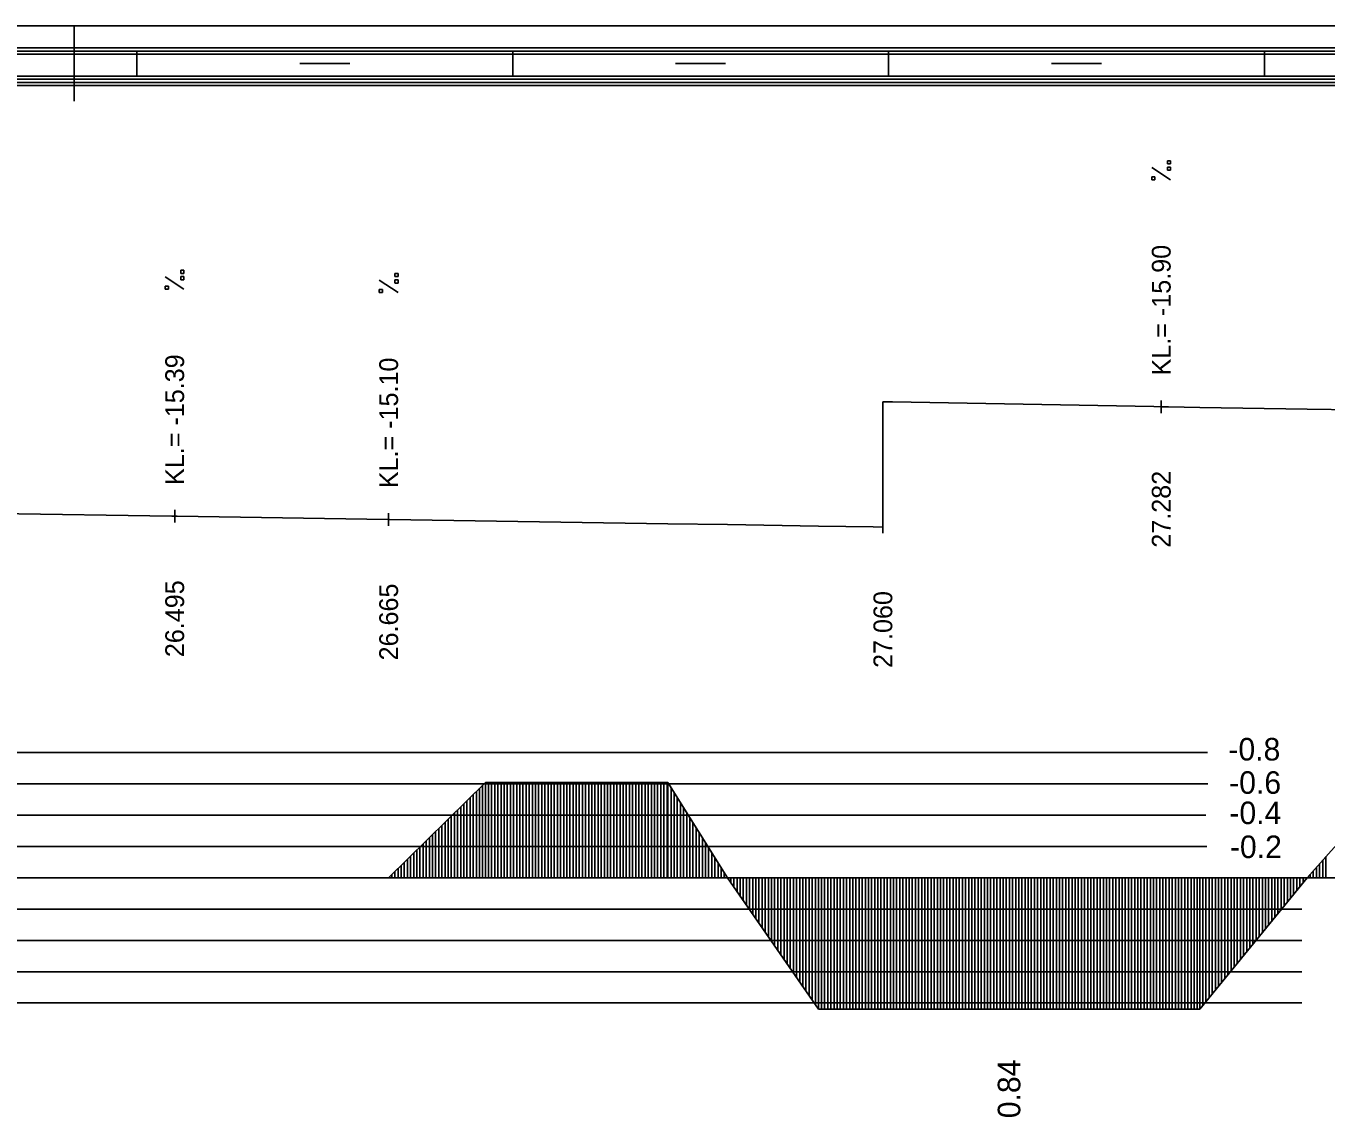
# Model space of a CAD drawing. Extents: x 2 to 10148, y 0 to 380.
# Drawn here: x 2936.2 to 3039.9, y 292.9 to 380 of the extents above; entities that cross this region are included whole.
import ezdxf

# ---------------------------------------------------------------- set-up
doc = ezdxf.new("R2010")
doc.units = 0
for name, color, linetype in [('NIVELETA_CARA', 7, 'Continuous'), ('NIVELETA_TEXT', 7, 'Continuous'), ('RAM', 7, 'Continuous'), ('ZRYCHL_CARA_C', 7, 'Continuous'), ('ZRYCHL_RASTR', 7, 'Continuous'), ('ZRYCHL_TEXT', 7, 'Continuous')]:
    doc.layers.add(name, color=color, linetype=linetype)

msp = doc.modelspace()

# ---------------------------------------------------------------- linework, layer by layer
at = {"layer": 'NIVELETA_CARA'}
for p, q in [((3004.55, 340), (3004.55, 350)), ((3004.55, 350), (3005.33, 349.99)), ((3005.33, 349.99), (3026.19, 349.61)), ((3026.77, 349.1), (3026.77, 350.1)), ((3026.19, 349.61), (3026.77, 349.6)), ((3026.77, 349.6), (3027.34, 349.59)), ((3027.34, 349.59), (3029.84, 349.55)), ((3029.84, 349.55), (3038.41, 349.41)), ((3038.41, 349.41), (3047.31, 349.27)), ((3004.55, 343.77), (3004.55, 346.25)), ((2918.57, 341.34), (2947.8, 340.86)), ((2947.8, 340.86), (2948.02, 340.86)), ((2948.02, 340.36), (2948.02, 341.36)), ((2948.02, 340.86), (2948.23, 340.86)), ((2948.23, 340.86), (2965.03, 340.6)), ((2965.03, 340.6), (2965.1, 340.6)), ((2965.1, 340.1), (2965.1, 341.1)), ((2965.1, 340.6), (2965.17, 340.59)), ((2965.17, 340.59), (2987.39, 340.26)), ((3004.55, 339.5), (3004.55, 340.5)), ((2987.39, 340.26), (2992.16, 340.19)), ((2992.16, 340.19), (2999.4, 340.08)), ((2999.4, 340.08), (3003.78, 340.01)), ((3003.78, 340.01), (3004.55, 340))]:
    msp.add_line(p, q, dxfattribs=at)
at = {"layer": 'NIVELETA_TEXT'}
for p, q in [((3027.51, 367.72), (3026.02, 368.71)), ((3027.52, 369.24), (3027.27, 369.24)), ((3027.27, 369.24), (3027.27, 369)), ((3027.27, 369), (3027.27, 368.99)), ((3027.27, 368.99), (3027.52, 368.99)), ((3027.52, 368.73), (3027.27, 368.73)), ((3027.27, 368.73), (3027.27, 368.48)), ((3027.27, 368.48), (3027.52, 368.48)), ((3027.27, 368.48), (3027.27, 368.48)), ((3027.52, 368.99), (3027.52, 369.24)), ((3027.52, 368.48), (3027.52, 368.73)), ((3026.27, 367.97), (3026.02, 367.97)), ((3026.02, 367.97), (3026.02, 367.73)), ((3026.02, 367.73), (3026.03, 367.72)), ((3026.02, 367.72), (3026.27, 367.72)), ((3026.27, 367.72), (3026.27, 367.97)), ((2948.76, 360.5), (2948.52, 360.5)), ((2948.52, 360.5), (2948.52, 360.26)), ((2948.52, 360.26), (2948.52, 360.25)), ((2948.52, 360.25), (2948.76, 360.25)), ((2948.76, 360.25), (2948.76, 360.5)), ((2965.85, 360.24), (2965.6, 360.24)), ((2965.6, 360.24), (2965.6, 360)), ((2965.85, 359.99), (2965.85, 360.24)), ((2948.76, 358.99), (2947.27, 359.98)), ((2947.52, 359.23), (2947.27, 359.23)), ((2947.27, 359.23), (2947.27, 358.99)), ((2947.52, 358.99), (2947.52, 359.23)), ((2948.76, 359.99), (2948.52, 359.99)), ((2948.52, 359.99), (2948.52, 359.75)), ((2948.52, 359.75), (2948.52, 359.74)), ((2948.52, 359.74), (2948.76, 359.74)), ((2948.76, 359.74), (2948.76, 359.99)), ((2965.85, 358.72), (2964.35, 359.71)), ((2965.6, 360), (2965.61, 359.99)), ((2965.6, 359.99), (2965.85, 359.99)), ((2965.85, 359.73), (2965.6, 359.73)), ((2965.6, 359.73), (2965.6, 359.49)), ((2965.6, 359.49), (2965.61, 359.48)), ((2965.6, 359.48), (2965.85, 359.48)), ((2965.85, 359.48), (2965.85, 359.73)), ((2947.27, 358.99), (2947.52, 358.99)), ((2947.27, 358.99), (2947.27, 358.99)), ((2964.6, 358.97), (2964.35, 358.97)), ((2964.35, 358.97), (2964.35, 358.73)), ((2964.35, 358.73), (2964.36, 358.72)), ((2964.35, 358.72), (2964.6, 358.72)), ((2964.6, 358.72), (2964.6, 358.97))]:
    msp.add_line(p, q, dxfattribs=at)
at = {"layer": 'RAM'}
for p, q in [((3155.54, 380), (2328.7, 380)), ((2940, 374), (2940, 380)), ((3155.54, 378.25), (2328.7, 378.25)), ((3155.54, 378), (2328.7, 378)), ((3155.54, 377.75), (2328.7, 377.75)), ((2945, 376), (2945, 378)), ((2975, 376), (2975, 378)), ((3005, 376), (3005, 378)), ((3035, 376), (3035, 378)), ((2958, 377), (2962, 377)), ((2988, 377), (2992, 377)), ((3018, 377), (3022, 377)), ((3155.54, 376), (2328.7, 376)), ((3155.54, 375.75), (2328.7, 375.75)), ((3155.54, 375.5), (2328.7, 375.5)), ((3155.54, 375.25), (2328.7, 375.25))]:
    msp.add_line(p, q, dxfattribs=at)
at = {"layer": 'ZRYCHL_CARA_C'}
for p, q in [((3038.41, 312), (3047.31, 322.02)), ((2965.1, 312), (2972.82, 319.6)), ((2971.85, 312), (2971.85, 318.64)), ((2972.1, 312), (2972.1, 318.89)), ((2972.35, 312), (2972.35, 319.14)), ((2972.6, 312), (2972.6, 319.38)), ((2972.82, 312), (2972.82, 319.6)), ((2972.82, 319.6), (2987.39, 319.6)), ((2973.07, 312), (2973.07, 319.6)), ((2973.32, 312), (2973.32, 319.6)), ((2973.57, 312), (2973.57, 319.6)), ((2973.82, 312), (2973.82, 319.6)), ((2974.07, 312), (2974.07, 319.6)), ((2974.32, 312), (2974.32, 319.6)), ((2974.57, 312), (2974.57, 319.6)), ((2974.82, 312), (2974.82, 319.6)), ((2975.07, 312), (2975.07, 319.6)), ((2975.32, 312), (2975.32, 319.6)), ((2975.57, 312), (2975.57, 319.6)), ((2975.82, 312), (2975.82, 319.6)), ((2976.07, 312), (2976.07, 319.6)), ((2976.32, 312), (2976.32, 319.6)), ((2976.57, 312), (2976.57, 319.6)), ((2976.82, 312), (2976.82, 319.6)), ((2977.07, 312), (2977.07, 319.6)), ((2977.32, 312), (2977.32, 319.6)), ((2977.57, 312), (2977.57, 319.6)), ((2977.82, 312), (2977.82, 319.6)), ((2978.07, 312), (2978.07, 319.6)), ((2978.32, 312), (2978.32, 319.6)), ((2978.57, 312), (2978.57, 319.6)), ((2978.82, 312), (2978.82, 319.6)), ((2979.07, 312), (2979.07, 319.6)), ((2979.32, 312), (2979.32, 319.6)), ((2979.57, 312), (2979.57, 319.6)), ((2979.82, 312), (2979.82, 319.6)), ((2980.07, 312), (2980.07, 319.6)), ((2980.32, 312), (2980.32, 319.6)), ((2980.57, 312), (2980.57, 319.6)), ((2980.82, 312), (2980.82, 319.6)), ((2981.07, 312), (2981.07, 319.6)), ((2981.32, 312), (2981.32, 319.6)), ((2981.57, 312), (2981.57, 319.6)), ((2981.82, 312), (2981.82, 319.6)), ((2982.07, 312), (2982.07, 319.6)), ((2982.32, 312), (2982.32, 319.6)), ((2982.57, 312), (2982.57, 319.6)), ((2982.82, 312), (2982.82, 319.6)), ((2983.07, 312), (2983.07, 319.6)), ((2983.32, 312), (2983.32, 319.6)), ((2983.57, 312), (2983.57, 319.6)), ((2983.82, 312), (2983.82, 319.6)), ((2984.07, 312), (2984.07, 319.6)), ((2984.32, 312), (2984.32, 319.6)), ((2984.57, 312), (2984.57, 319.6)), ((2984.82, 312), (2984.82, 319.6)), ((2985.07, 312), (2985.07, 319.6)), ((2985.32, 312), (2985.32, 319.6)), ((2985.57, 312), (2985.57, 319.6)), ((2985.82, 312), (2985.82, 319.6)), ((2986.07, 312), (2986.07, 319.6)), ((2986.32, 312), (2986.32, 319.6)), ((2986.57, 312), (2986.57, 319.6)), ((2986.82, 312), (2986.82, 319.6)), ((2987.07, 312), (2987.07, 319.6)), ((2987.32, 312), (2987.32, 319.6)), ((2987.39, 312), (2987.39, 319.6)), ((2987.39, 319.6), (2992.16, 312)), ((2987.64, 312), (2987.64, 319.2)), ((2987.89, 312), (2987.89, 318.8)), ((2970.85, 312), (2970.85, 317.66)), ((2971.1, 312), (2971.1, 317.91)), ((2971.35, 312), (2971.35, 318.15)), ((2971.6, 312), (2971.6, 318.4)), ((2988.14, 312), (2988.14, 318.4)), ((2988.39, 312), (2988.39, 318)), ((2988.64, 312), (2988.64, 317.61)), ((2969.85, 312), (2969.85, 316.68)), ((2970.1, 312), (2970.1, 316.92)), ((2970.35, 312), (2970.35, 317.17)), ((2970.6, 312), (2970.6, 317.41)), ((2988.89, 312), (2988.89, 317.21)), ((2989.14, 312), (2989.14, 316.81)), ((2968.85, 312), (2968.85, 315.69)), ((2969.1, 312), (2969.1, 315.94)), ((2969.35, 312), (2969.35, 316.18)), ((2969.6, 312), (2969.6, 316.43)), ((2989.39, 312), (2989.39, 316.41)), ((2989.64, 312), (2989.64, 316.01)), ((2989.89, 312), (2989.89, 315.61)), ((2967.6, 312), (2967.6, 314.46)), ((2967.85, 312), (2967.85, 314.71)), ((2968.1, 312), (2968.1, 314.95)), ((2968.35, 312), (2968.35, 315.2)), ((2968.6, 312), (2968.6, 315.45)), ((2990.14, 312), (2990.14, 315.22)), ((2990.39, 312), (2990.39, 314.82)), ((2966.6, 312), (2966.6, 313.48)), ((2966.85, 312), (2966.85, 313.72)), ((2967.1, 312), (2967.1, 313.97)), ((2967.35, 312), (2967.35, 314.21)), ((2990.64, 312), (2990.64, 314.42)), ((2990.89, 312), (2990.89, 314.02)), ((2991.14, 312), (2991.14, 313.62)), ((3039.66, 312), (3039.66, 313.41)), ((3039.91, 312), (3039.91, 313.69)), ((2965.6, 312), (2965.6, 312.49)), ((2965.85, 312), (2965.85, 312.74)), ((2966.1, 312), (2966.1, 312.98)), ((2966.35, 312), (2966.35, 313.23)), ((2991.39, 312), (2991.39, 313.23)), ((2991.64, 312), (2991.64, 312.83)), ((2991.89, 312), (2991.89, 312.43)), ((3038.91, 312), (3038.91, 312.56)), ((3039.16, 312), (3039.16, 312.84)), ((3039.41, 312), (3039.41, 313.12)), ((2328.7, 312), (3155.54, 312)), ((2965.35, 312), (2965.35, 312.25)), ((2992.14, 312), (2992.14, 312.03)), ((2992.16, 312), (2999.4, 301.5)), ((2992.41, 312), (2992.41, 311.64)), ((2992.66, 312), (2992.66, 311.28)), ((2992.91, 312), (2992.91, 310.91)), ((2993.16, 312), (2993.16, 310.55)), ((2993.41, 312), (2993.41, 310.19)), ((2993.66, 312), (2993.66, 309.83)), ((2993.91, 312), (2993.91, 309.46)), ((2994.16, 312), (2994.16, 309.1)), ((2994.41, 312), (2994.41, 308.74)), ((2994.66, 312), (2994.66, 308.38)), ((2994.91, 312), (2994.91, 308.01)), ((2995.16, 312), (2995.16, 307.65)), ((2995.41, 312), (2995.41, 307.29)), ((2995.66, 312), (2995.66, 306.93)), ((2995.91, 312), (2995.91, 306.56)), ((2996.16, 312), (2996.16, 306.2)), ((2996.41, 312), (2996.41, 305.84)), ((2996.66, 312), (2996.66, 305.48)), ((2996.91, 312), (2996.91, 305.11)), ((2997.16, 312), (2997.16, 304.75)), ((2997.41, 312), (2997.41, 304.39)), ((2997.66, 312), (2997.66, 304.03)), ((2997.91, 312), (2997.91, 303.66)), ((2998.16, 312), (2998.16, 303.3)), ((2998.41, 312), (2998.41, 302.94)), ((2998.66, 312), (2998.66, 302.58)), ((2998.91, 312), (2998.91, 302.21)), ((2999.16, 312), (2999.16, 301.85)), ((2999.4, 312), (2999.4, 301.5)), ((2999.65, 312), (2999.65, 301.5)), ((2999.9, 312), (2999.9, 301.5)), ((3000.15, 312), (3000.15, 301.5)), ((3000.4, 312), (3000.4, 301.5)), ((3000.65, 312), (3000.65, 301.5)), ((3000.9, 312), (3000.9, 301.5)), ((3001.15, 312), (3001.15, 301.5)), ((3001.4, 312), (3001.4, 301.5)), ((3001.65, 312), (3001.65, 301.5)), ((3001.9, 312), (3001.9, 301.5)), ((3002.15, 312), (3002.15, 301.5)), ((3002.4, 312), (3002.4, 301.5)), ((3002.65, 312), (3002.65, 301.5)), ((3002.9, 312), (3002.9, 301.5)), ((3003.15, 312), (3003.15, 301.5)), ((3003.4, 312), (3003.4, 301.5)), ((3003.65, 312), (3003.65, 301.5)), ((3003.9, 312), (3003.9, 301.5)), ((3004.15, 312), (3004.15, 301.5)), ((3004.4, 312), (3004.4, 301.5)), ((3004.65, 312), (3004.65, 301.5)), ((3004.9, 312), (3004.9, 301.5)), ((3005.15, 312), (3005.15, 301.5)), ((3005.4, 312), (3005.4, 301.5)), ((3005.65, 312), (3005.65, 301.5)), ((3005.9, 312), (3005.9, 301.5)), ((3006.15, 312), (3006.15, 301.5)), ((3006.4, 312), (3006.4, 301.5)), ((3006.65, 312), (3006.65, 301.5)), ((3006.9, 312), (3006.9, 301.5)), ((3007.15, 312), (3007.15, 301.5)), ((3007.4, 312), (3007.4, 301.5)), ((3007.65, 312), (3007.65, 301.5)), ((3007.9, 312), (3007.9, 301.5)), ((3008.15, 312), (3008.15, 301.5)), ((3008.4, 312), (3008.4, 301.5)), ((3008.65, 312), (3008.65, 301.5)), ((3008.9, 312), (3008.9, 301.5)), ((3009.15, 312), (3009.15, 301.5)), ((3009.4, 312), (3009.4, 301.5)), ((3009.65, 312), (3009.65, 301.5)), ((3009.9, 312), (3009.9, 301.5)), ((3010.15, 312), (3010.15, 301.5)), ((3010.4, 312), (3010.4, 301.5)), ((3010.65, 312), (3010.65, 301.5)), ((3010.9, 312), (3010.9, 301.5)), ((3011.15, 312), (3011.15, 301.5)), ((3011.4, 312), (3011.4, 301.5)), ((3011.65, 312), (3011.65, 301.5)), ((3011.9, 312), (3011.9, 301.5)), ((3012.15, 312), (3012.15, 301.5)), ((3012.4, 312), (3012.4, 301.5)), ((3012.65, 312), (3012.65, 301.5)), ((3012.9, 312), (3012.9, 301.5)), ((3013.15, 312), (3013.15, 301.5)), ((3013.4, 312), (3013.4, 301.5)), ((3013.65, 312), (3013.65, 301.5)), ((3013.9, 312), (3013.9, 301.5)), ((3014.15, 312), (3014.15, 301.5)), ((3014.4, 312), (3014.4, 301.5)), ((3014.65, 312), (3014.65, 301.5)), ((3014.9, 312), (3014.9, 301.5)), ((3015.15, 312), (3015.15, 301.5)), ((3015.4, 312), (3015.4, 301.5)), ((3015.65, 312), (3015.65, 301.5)), ((3015.9, 312), (3015.9, 301.5)), ((3016.15, 312), (3016.15, 301.5)), ((3016.4, 312), (3016.4, 301.5)), ((3016.65, 312), (3016.65, 301.5)), ((3016.9, 312), (3016.9, 301.5)), ((3017.15, 312), (3017.15, 301.5)), ((3017.4, 312), (3017.4, 301.5)), ((3017.65, 312), (3017.65, 301.5)), ((3017.9, 312), (3017.9, 301.5)), ((3018.15, 312), (3018.15, 301.5)), ((3018.4, 312), (3018.4, 301.5)), ((3018.65, 312), (3018.65, 301.5)), ((3018.9, 312), (3018.9, 301.5)), ((3019.15, 312), (3019.15, 301.5)), ((3019.4, 312), (3019.4, 301.5)), ((3019.65, 312), (3019.65, 301.5)), ((3019.9, 312), (3019.9, 301.5)), ((3020.15, 312), (3020.15, 301.5)), ((3020.4, 312), (3020.4, 301.5)), ((3020.65, 312), (3020.65, 301.5)), ((3020.9, 312), (3020.9, 301.5)), ((3021.15, 312), (3021.15, 301.5)), ((3021.4, 312), (3021.4, 301.5)), ((3021.65, 312), (3021.65, 301.5)), ((3021.9, 312), (3021.9, 301.5)), ((3022.15, 312), (3022.15, 301.5)), ((3022.4, 312), (3022.4, 301.5)), ((3022.65, 312), (3022.65, 301.5)), ((3022.9, 312), (3022.9, 301.5)), ((3023.15, 312), (3023.15, 301.5)), ((3023.4, 312), (3023.4, 301.5)), ((3023.65, 312), (3023.65, 301.5)), ((3023.9, 312), (3023.9, 301.5)), ((3024.15, 312), (3024.15, 301.5)), ((3024.4, 312), (3024.4, 301.5)), ((3024.65, 312), (3024.65, 301.5)), ((3024.9, 312), (3024.9, 301.5)), ((3025.15, 312), (3025.15, 301.5)), ((3025.4, 312), (3025.4, 301.5)), ((3025.65, 312), (3025.65, 301.5)), ((3025.9, 312), (3025.9, 301.5)), ((3026.15, 312), (3026.15, 301.5)), ((3026.4, 312), (3026.4, 301.5)), ((3026.65, 312), (3026.65, 301.5)), ((3026.9, 312), (3026.9, 301.5)), ((3027.15, 312), (3027.15, 301.5)), ((3027.4, 312), (3027.4, 301.5)), ((3027.65, 312), (3027.65, 301.5)), ((3027.9, 312), (3027.9, 301.5)), ((3028.15, 312), (3028.15, 301.5)), ((3028.4, 312), (3028.4, 301.5)), ((3028.65, 312), (3028.65, 301.5)), ((3028.9, 312), (3028.9, 301.5)), ((3029.15, 312), (3029.15, 301.5)), ((3029.4, 312), (3029.4, 301.5)), ((3029.65, 312), (3029.65, 301.5)), ((3029.84, 312), (3029.84, 301.5)), ((3029.84, 301.5), (3038.41, 312)), ((3030.09, 312), (3030.09, 301.81)), ((3030.34, 312), (3030.34, 302.12)), ((3030.59, 312), (3030.59, 302.42)), ((3030.84, 312), (3030.84, 302.73)), ((3031.09, 312), (3031.09, 303.04)), ((3031.34, 312), (3031.34, 303.34)), ((3031.59, 312), (3031.59, 303.65)), ((3031.84, 312), (3031.84, 303.95)), ((3032.09, 312), (3032.09, 304.26)), ((3032.34, 312), (3032.34, 304.57)), ((3032.59, 312), (3032.59, 304.87)), ((3032.84, 312), (3032.84, 305.18)), ((3033.09, 312), (3033.09, 305.48)), ((3033.34, 312), (3033.34, 305.79)), ((3033.59, 312), (3033.59, 306.1)), ((3033.84, 312), (3033.84, 306.4)), ((3034.09, 312), (3034.09, 306.71)), ((3034.34, 312), (3034.34, 307.02)), ((3034.59, 312), (3034.59, 307.32)), ((3034.84, 312), (3034.84, 307.63)), ((3035.09, 312), (3035.09, 307.93)), ((3035.34, 312), (3035.34, 308.24)), ((3035.59, 312), (3035.59, 308.55)), ((3035.84, 312), (3035.84, 308.85)), ((3036.09, 312), (3036.09, 309.16)), ((3036.34, 312), (3036.34, 309.47)), ((3036.59, 312), (3036.59, 309.77)), ((3036.84, 312), (3036.84, 310.08)), ((3037.09, 312), (3037.09, 310.38)), ((3037.34, 312), (3037.34, 310.69)), ((3037.59, 312), (3037.59, 311)), ((3037.84, 312), (3037.84, 311.3)), ((3038.09, 312), (3038.09, 311.61)), ((3038.34, 312), (3038.34, 311.92)), ((3038.66, 312), (3038.66, 312.28)), ((2999.4, 301.5), (3029.84, 301.5))]:
    msp.add_line(p, q, dxfattribs=at)
at = {"layer": 'ZRYCHL_RASTR'}
for p, q in [((2632, 322), (3030.47, 322)), ((2632, 319.5), (3030.48, 319.5)), ((2632, 317), (3030.32, 317)), ((2632, 314.5), (3030.4, 314.5)), ((2842, 309.5), (3038, 309.5)), ((2842, 307), (3038, 307)), ((2842, 304.5), (3038, 304.5)), ((2842, 302), (3038, 302))]:
    msp.add_line(p, q, dxfattribs=at)

# ---------------------------------------------------------------- texts
at = {"layer": 'NIVELETA_TEXT'}
for s, p in [('KL.= -15.90', (3027.52, 352.1)), ('KL.= -15.39', (2948.77, 343.36)), ('KL.= -15.10', (2965.85, 343.1)), ('27.282', (3027.52, 338.35)), ('26.495', (2948.77, 329.61)), ('26.665', (2965.85, 329.35)), ('27.060', (3005.3, 328.75))]:
    msp.add_text(s, height=1.5, rotation=90, dxfattribs=at).set_placement(p)
at = {"layer": 'ZRYCHL_TEXT'}
for s, p in [('-0.8', (3032.13, 321.36)), ('-0.6', (3032.19, 318.7)), ('-0.4', (3032.21, 316.28)), ('-0.2', (3032.25, 313.57))]:
    msp.add_text(s, height=1.8, dxfattribs=at).set_placement(p)
msp.add_text('0.84', height=1.8, rotation=90, dxfattribs=at).set_placement((3015.52, 292.8))

doc.saveas('drawing.dxf')
